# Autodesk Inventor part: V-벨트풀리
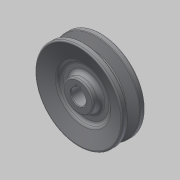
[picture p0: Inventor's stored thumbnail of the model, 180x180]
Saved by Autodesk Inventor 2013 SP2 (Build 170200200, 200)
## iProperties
Created: 2016-08
Part Number: V-벨트풀리
Material: 알루미늄 6061
Document SubType Name: Modeling
Designer: mduedu
Density: 2.71 g/cm^3
Author: mduedu
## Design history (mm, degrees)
sketch "스케치1"
  geometry: L1 (0, 9.5)-(0, -9.5); L2 (0, 9.5)-(35, 9.5); L3 (35, 9.5)-(35, 4.825); L4 (35, 4.825)-(26, 2.074); L5 (26, 2.074)-(26, 0); L6 (0, 0)-(26, 0); L7 (0, -9.5)-(35, -9.5); L8 (35, -9.5)-(35, -4.825); L9 (35, -4.825)-(26, -2.074); L10 (26, -2.074)-(26, 0); L11 (32.3, 9.5)-(32.3, -9.5); 3 further points
  constraints: 22 end point, 6 point on line, 4 perpendicular, 3 symmetric about line, 1 coincident, 1 horizontal alignment, 1 midpoint, 1 parallel, 1 vertical
  dimensions: "d0" = 19 distance of L1.start L1.end; "d2" = 70 diameter of L8 L1; "d4" = 6.3 distance between parallel lines of L10 L11; "d5" = 2.7 distance between parallel lines of L11 L8; "d6" = 8 distance of point (32.3, -4) point (32.3, 4); "d7" = 34 deg angle of L9 L4
revolve "회전1" sketch "스케치1" stored, may be unused: angle "d8" = 90 deg
sketch "스케치2"
  geometry: L1 (-2, 0)-(2, 0); L2 (2, 0)-(2, 7.8); L3 (2, 7.8)-(-2, 7.8); L4 (-2, 7.8)-(-2, 0); C1 r 6 at (0, 0); 2 further points
  constraints: 8 end point, 2 coincident, 2 parallel, 1 centre point, 1 horizontal, 1 midpoint, 1 perpendicular
  dimensions: "d9" = 12 diameter of C1; "d11" = 4 distance of L2.end L3.end; "d12" = 7.8 distance of L1.end L2.end
extrude "돌출1" cut sketch "스케치2" stored distance "d13" = 10; taper "d14" = 0 deg
sketch "스케치3"
  geometry: L1 (35, 4.825)-(26, 2.074) reference; L2 (26, 2.074)-(26, -2.074) reference; L3 (0, 0)-(26, 0); L4 (35, 9.5)-(35, 4.825) reference; L5 (-35, 9.5)-(35, 9.5) reference; L6 (35, 9.5)-(21, 5.22); L7 (21, 5.22)-(21, 3); L8 (21, 3)-(12, 3); L9 (12, 3)-(12, 9.5); L10 (0, 9.5)-(0, -9.5); L11 (5.657, -9.5)-(-6, -9.5) reference; L12 (12, 9.5)-(35, 9.5)
  constraints: 14 end point, 3 midpoint, 2 parallel, 2 perpendicular, 2 point on line, 1 collinear, 1 horizontal
  dimensions: "d15" = 3 distance between parallel lines of L3 L8; "d17" = 42 diameter of L7 L10; "d18" = 24 diameter of L9 L10
revolve "회전2" sketch "스케치3" stored, may be unused: angle "d19" = 90 deg
fillet "모깎기1" dims "d20" = 0.5, "d21" = 1, "d22" = 1
fillet "모깎기2" dims "d23" = 3
fillet "모깎기3" dims "d24" = 3
fillet "모깎기4" dims "d25" = 3
chamfer "모따기1" distance "d26" = 0.5; stored, may be unused: second distance "d27" = 2, angle "d28" = 45 deg
fillet "모깎기5" dims "d29" = 1
node "솔리드1"
mirror "대칭1"
